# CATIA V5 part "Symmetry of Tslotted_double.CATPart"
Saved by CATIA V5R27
Part number: Symmetry of Tslotted_double
Bounding box of the stored display mesh (mm): x -19.05 to 19.05, y -19.05 to 19.05, z -381 to 381
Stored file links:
  \\triton.meca.polymtl.ca\usagers\zaoue\profiles\Desktop\varm_ass\structure prismatique\Symmetry of Tslotted_double.CATPart
  \\triton.meca.polymtl.ca\usagers\zaoue\profiles\Desktop\varm_ass\structure prismatique\Alu_Tslot_double.CATPart
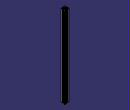
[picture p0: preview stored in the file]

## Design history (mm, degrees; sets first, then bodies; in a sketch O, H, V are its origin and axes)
Body1 (main body)
  Body2 "Corps du corps principal d'origine"
    Solid1: linked copy from another document
  Assemble1: tool Body2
